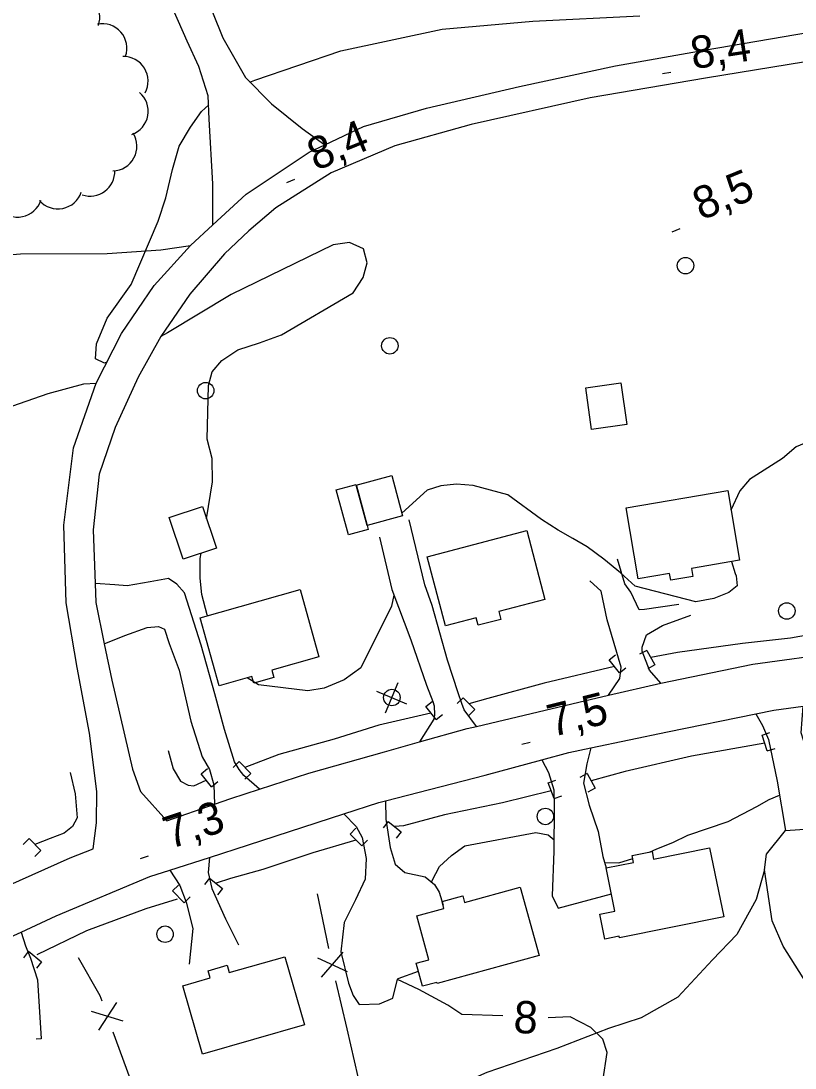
# Model space of a CAD drawing. Extents: x 362852 to 366875, y 5563573 to 5566479.
# Drawn here: x 364831.6 to 364925.6, y 5564861.3 to 5564988.5 of the extents above; entities that cross this region are included whole.
import ezdxf

# ---------------------------------------------------------------- set-up
doc = ezdxf.new("R2010")
doc.units = 0
for name, color, linetype in [('Niveau 19', 7, 'Continuous'), ('Niveau 2', 7, 'Continuous'), ('Niveau 21', 7, 'Continuous'), ('Niveau 22', 7, 'Continuous'), ('Niveau 26', 7, 'Continuous'), ('Niveau 3', 7, 'Continuous'), ('Niveau 31', 7, 'Continuous'), ('Niveau 36', 7, 'Continuous'), ('Niveau 37', 7, 'Continuous'), ('Niveau 4', 7, 'Continuous'), ('Niveau 44', 7, 'Continuous')]:
    doc.layers.add(name, color=color, linetype=linetype)

msp = doc.modelspace()

# ---------------------------------------------------------------- linework, layer by layer
at = {"layer": 'Niveau 19'}
for points in [[(364854.86, 5564963.71), (364854.88, 5564968.69), (364854.45, 5564976.57), (364854.32, 5564979.41), (364853.19, 5564982.96), (364851.76, 5564986.02), (364850.08, 5564989.79)], [(364854.82, 5564989.58), (364856.09, 5564986.44), (364858.84, 5564981.61), (364862, 5564978.41), (364865.72, 5564975.42), (364868.47, 5564973.43)], [(364886.94, 5564902.77), (364885.41, 5564904.8), (364885.15, 5564905.56), (364884.68, 5564906.86), (364883.39, 5564910.83), (364881.52, 5564917.48), (364880.64, 5564919.98), (364878.73, 5564927.86)], [(364875.13, 5564925.75), (364876.64, 5564919.39), (364878.93, 5564913.29), (364880.86, 5564907.78), (364881.62, 5564905.79), (364881.79, 5564905.29), (364881.81, 5564904.18), (364881.73, 5564903.65), (364880.01, 5564900.89)], [(364911.5, 5564917.6), (364907.35, 5564916.98), (364906.71, 5564916.95), (364905.67, 5564919.08), (364904.97, 5564920.11), (364904.08, 5564923.11)], [(364860.54, 5564895.13), (364858.63, 5564896.81), (364858.09, 5564897.52), (364857.51, 5564898.47), (364856.3, 5564902.41), (364855.11, 5564906.74), (364853.45, 5564912.65), (364851.44, 5564919.02), (364850.52, 5564920.07), (364849.49, 5564920.76), (364847.27, 5564920.33), (364844.46, 5564919.84), (364842.98, 5564919.97), (364840.56, 5564920.14)], [(364902.98, 5564906.55), (364904.34, 5564908.61), (364904.49, 5564909.96), (364902.8, 5564915.71), (364902.07, 5564919.21), (364900.69, 5564920.47)], [(364909.33, 5564908.04), (364907.94, 5564909.61), (364907.08, 5564911.91), (364907.07, 5564912.4), (364907.57, 5564913.88), (364909.54, 5564915.04), (364912.97, 5564916.29)], [(364841.68, 5564912.79), (364844.18, 5564913.81), (364846.89, 5564914.77), (364848.29, 5564914.93), (364848.99, 5564914.59), (364849.56, 5564912.85), (364850.79, 5564909.62), (364852.2, 5564903.4), (364853.57, 5564899.06), (364854.46, 5564897.55), (364855, 5564895.66), (364855.09, 5564893.33)], [(364920.89, 5564904.29), (364921.67, 5564902.88), (364922.4, 5564901.18), (364923.49, 5564896.13), (364924.48, 5564890.14), (364927.98, 5564890.37), (364927.08, 5564896.3), (364927.24, 5564899.31), (364926.39, 5564901.97), (364926.62, 5564905.23)], [(364900.83, 5564900.17), (364900.35, 5564898.21), (364899.95, 5564895.87), (364900.62, 5564893.19), (364901.72, 5564890.02), (364902.29, 5564886.97), (364902.68, 5564885.57)], [(364894.85, 5564898.71), (364895.66, 5564897.18), (364896.33, 5564895.05), (364896.38, 5564892.99), (364896.34, 5564887.61), (364896.13, 5564882.19), (364896.84, 5564880.67), (364903.33, 5564882.43)], [(364875.86, 5564893.72), (364875.89, 5564891.48), (364876.44, 5564888.06), (364877.03, 5564886.04), (364878.21, 5564885), (364880.69, 5564884.49), (364881.81, 5564883.58), (364882.38, 5564882.64), (364882.87, 5564881.04)], [(364870.81, 5564892.14), (364872.29, 5564890.6), (364873.01, 5564889.29), (364873.52, 5564886.73), (364873.39, 5564884.21), (364872.2, 5564881.7), (364870.82, 5564878.94), (364870.43, 5564875.37), (364871.37, 5564871.59), (364871.93, 5564870.08), (364872.67, 5564868.98), (364875.15, 5564869.08), (364876.74, 5564869.74), (364877.34, 5564872.04), (364877.42, 5564872.14), (364879.86, 5564873.04)], [(364854.49, 5564886.86), (364854.32, 5564885.02), (364854.75, 5564883.08), (364856.41, 5564879.38), (364857.98, 5564876.21)], [(364849.64, 5564885.3), (364850.85, 5564883.44), (364851.63, 5564881.4), (364852.43, 5564878.23), (364851.98, 5564873.89)], [(364831.57, 5564877.78), (364832.09, 5564876.11), (364832.7, 5564874.6), (364833.56, 5564871.98), (364834, 5564864.79), (364833.41, 5564864.78)]]:
    msp.add_lwpolyline(points, dxfattribs=at)
at = {"layer": 'Niveau 2'}
for points in [[(364859.38, 5564981.06), (364859.99, 5564981.31), (364870.43, 5564984.88), (364882.75, 5564987.49), (364893.77, 5564988.45), (364906.77, 5564989.1)], [(364842, 5564947.04), (364841.69, 5564946.91), (364840.6, 5564947.45), (364840.72, 5564949.25), (364842.03, 5564952.39), (364844.94, 5564956.46), (364848.22, 5564964.15), (364849.15, 5564967.01), (364849.96, 5564970.46), (364850.78, 5564973.28), (364852.18, 5564975.6), (364853.5, 5564977.51), (364854.37, 5564978.3)], [(364860.53, 5564949.36), (364863.22, 5564950.35), (364871.92, 5564955.44), (364873.13, 5564957.31), (364873.62, 5564959.12), (364873.17, 5564960.8), (364871.48, 5564961.59), (364869.51, 5564961.27), (364857.1, 5564955.27), (364849.36, 5564950.58), (364848.56, 5564950.14)], [(364854.12, 5564928.01), (364854.84, 5564932.48), (364854.79, 5564935.31), (364854.19, 5564937.67), (364854.35, 5564944.2), (364854.78, 5564945.86), (364855.95, 5564947.22), (364857.9, 5564948.52), (364860.53, 5564949.36)], [(364931.23, 5564933.18), (364930.52, 5564935.46), (364928.65, 5564937.3), (364927.26, 5564937.34), (364925.78, 5564936.73), (364924.14, 5564935.31), (364920.1, 5564932.77), (364918.92, 5564931.41), (364917.86, 5564929.06)], [(364917.94, 5564922.8), (364918.36, 5564921.36), (364918.49, 5564921.05), (364918.61, 5564919.85), (364917.58, 5564919.05), (364915.77, 5564918.31), (364913.59, 5564917.9), (364906.22, 5564919.82), (364904.43, 5564921.44), (364902.39, 5564923.08), (364900.39, 5564924.61), (364898.62, 5564925.62), (364896.84, 5564926.62), (364894.82, 5564927.9), (364890.72, 5564930.92), (364886.53, 5564932.05), (364884.49, 5564932.19), (364882.57, 5564932.02), (364880.94, 5564931.47), (364877.86, 5564928.68)], [(364854.23, 5564916.24), (364854.2, 5564916.31), (364853.55, 5564918.78), (364853.34, 5564920.8), (364853.35, 5564923.17), (364853.45, 5564923.81)], [(364876.89, 5564918.71), (364876.59, 5564917.37), (364872.86, 5564909.87), (364870.86, 5564908.42), (364868.42, 5564907.41), (364866.44, 5564907.09), (364860.43, 5564907.83), (364859.06, 5564908.67)], [(364907.94, 5564887.5), (364908.86, 5564887.88), (364910.77, 5564888.66), (364912.63, 5564889.56), (364917.53, 5564891.21), (364921, 5564893.02), (364922.5, 5564893.89), (364923.77, 5564894.42)], [(364881.5, 5564883.83), (364881.55, 5564884.03), (364882.44, 5564885.76), (364883.88, 5564887.1), (364885.5, 5564888.27), (364894.15, 5564889.86), (364895.62, 5564889.6), (364896.35, 5564889)], [(364902.5, 5564886.22), (364904.22, 5564886.2), (364905.91, 5564886.72)], [(364890.14, 5564867.61), (364885.16, 5564867.76), (364883.44, 5564868.91), (364879.93, 5564870.81), (364877.94, 5564871.73), (364877.34, 5564872.02)], [(364902.27, 5564859.68), (364902.82, 5564863.14), (364902.27, 5564864.78), (364900.83, 5564866.17), (364898.3, 5564867.48), (364895.65, 5564867.37)]]:
    msp.add_lwpolyline(points, dxfattribs=at)
at = {"layer": 'Niveau 21'}
for points in [[(364840.31, 5564887.88), (364840.72, 5564891.07), (364840.79, 5564894.85), (364839.88, 5564901.95), (364838.37, 5564909.91), (364837.05, 5564917.77), (364836.78, 5564927.24), (364837.94, 5564936.62), (364840.71, 5564944.48), (364843.77, 5564950.53), (364847.74, 5564956.34), (364852.15, 5564961.22), (364854.86, 5564963.71), (364858.91, 5564967.44), (364866.58, 5564972.54), (364868.47, 5564973.43), (364873.2, 5564975.66), (364880.86, 5564977.9), (364892.17, 5564980.53), (364903.82, 5564983.04), (364914.6, 5564984.95), (364927.39, 5564987.13), (364940.08, 5564988.46), (364954.57, 5564989.62)], [(364930.88, 5564984.16), (364914.75, 5564981.54), (364900.76, 5564979.17), (364886.28, 5564975.93), (364876.98, 5564973.32), (364869.24, 5564970.05), (364862.54, 5564965.78), (364859.25, 5564962.99), (364856.28, 5564960.2), (364852.07, 5564955.28), (364848.57, 5564950.16), (364845.8, 5564945.22), (364842.99, 5564939.09), (364841.04, 5564933.42), (364840.33, 5564926.65), (364840.56, 5564920.14), (364840.65, 5564917.83), (364841.68, 5564912.79), (364842.59, 5564908.37), (364845.11, 5564897.58), (364846.07, 5564894.86), (364849.29, 5564891.31)], [(364849.29, 5564891.31), (364855.09, 5564893.33), (364857.06, 5564894.02), (364860.54, 5564895.13), (364866.54, 5564897.07), (364875.73, 5564899.7), (364880.01, 5564900.89), (364885.8, 5564902.5), (364886.94, 5564902.77), (364899.35, 5564905.7), (364902.98, 5564906.55), (364909.33, 5564908.04), (364920.52, 5564910.32), (364931.16, 5564911.81), (364939.02, 5564912.98), (364945.51, 5564913.95), (364954.89, 5564914.62), (364958.04, 5564914.85), (364962.78, 5564915.16), (364967.33, 5564915.46), (364973.94, 5564915.83), (364977.36, 5564916.03), (364989.51, 5564916.41), (364998.46, 5564916.49)], [(364827.38, 5564875.85), (364831.57, 5564877.78), (364835.85, 5564879.76), (364847.22, 5564884.53), (364849.64, 5564885.3), (364854.49, 5564886.86), (364859.2, 5564888.38), (364870.81, 5564892.14), (364875.05, 5564893.52), (364875.86, 5564893.72), (364887.99, 5564896.83), (364894.85, 5564898.71), (364898.14, 5564899.6), (364900.83, 5564900.17), (364910.14, 5564902.11), (364920.89, 5564904.29), (364923.08, 5564904.73), (364926.62, 5564905.23)], [(364829.85, 5564883.35), (364837.53, 5564886.79), (364840.31, 5564887.88)]]:
    msp.add_lwpolyline(points, dxfattribs=at)
at = {"layer": 'Niveau 22'}
for points in [[(364793.73, 5564950.34), (364799.32, 5564952.65), (364803.9, 5564954.39), (364808.18, 5564955.75), (364820.42, 5564959.27), (364831.51, 5564960.2), (364842.03, 5564960.22), (364848.54, 5564960.7), (364852.15, 5564961.22)], [(364782.44, 5564942.02), (364785.31, 5564940.9), (364787.9, 5564939.43), (364789.49, 5564938.7), (364792.51, 5564937.2), (364797.93, 5564935.27), (364801.74, 5564934.48), (364810.07, 5564935.5), (364820.5, 5564938.4), (364829.62, 5564941.41), (364834.87, 5564943.23), (364839.2, 5564944.41), (364840.71, 5564944.48)], [(365020.02, 5564865.79), (365014.94, 5564866.34), (365007.86, 5564865.87), (364995.41, 5564864.38), (364983.3, 5564862.86), (364972.1, 5564861.76), (364961.45, 5564860.83), (364955.92, 5564859.76), (364952.98, 5564858.92), (364950.44, 5564858.17), (364948.74, 5564858.09), (364943.36, 5564858.58), (364938.36, 5564859.06), (364934.59, 5564859.41), (364933.55, 5564859.97), (364932.52, 5564860.97), (364931.14, 5564863.62), (364929.76, 5564866.52), (364928.08, 5564869.91), (364924.21, 5564876.05), (364922.85, 5564879.14), (364921.92, 5564885.35), (364922.19, 5564887.26), (364924.48, 5564890.14)], [(364921.92, 5564885.35), (364920.9, 5564881.75), (364918.56, 5564877.49), (364915.62, 5564874.41), (364911.41, 5564869.87), (364906.94, 5564867.34), (364902.99, 5564866.08), (364896.7, 5564863.64), (364888.2, 5564860.73), (364885.33, 5564859.48), (364879.23, 5564856.81), (364873.61, 5564854.18), (364866.25, 5564851.93), (364860.8, 5564850.77), (364848.56, 5564849.72), (364841.14, 5564848.19), (364831.86, 5564845.06), (364821.27, 5564841.41), (364820.46, 5564841.14), (364809.21, 5564837.9), (364799.25, 5564836.01), (364795.21, 5564835.22)]]:
    msp.add_lwpolyline(points, dxfattribs=at)
at = {"layer": 'Niveau 26'}
for p, q in [((364907.63, 5564912.01), (364906.75, 5564911.53)), ((364907.63, 5564912.01), (364908.6, 5564910.25)), ((364903.04, 5564910.85), (364903.83, 5564911.47)), ((364904.31, 5564909.27), (364903.04, 5564910.85)), ((364904.31, 5564909.27), (364905.09, 5564909.9)), ((364908.6, 5564910.25), (364907.74, 5564909.77)), ((364880.76, 5564905.17), (364881.53, 5564905.79)), ((364885.3, 5564906.24), (364884.59, 5564905.54)), ((364885.3, 5564906.24), (364886.72, 5564904.81)), ((364882.03, 5564903.59), (364880.76, 5564905.17)), ((364882.03, 5564903.59), (364882.81, 5564904.21)), ((364886.72, 5564904.81), (364886.01, 5564904.11)), ((364921.63, 5564901.72), (364922.59, 5564902.02)), ((364922.26, 5564899.79), (364921.63, 5564901.72)), ((364922.26, 5564899.79), (364923.22, 5564900.1)), ((364858.06, 5564898.5), (364857.35, 5564897.78)), ((364858.06, 5564898.5), (364859.49, 5564897.05)), ((364853.46, 5564897), (364854.22, 5564897.64)), ((364854.72, 5564895.44), (364853.46, 5564897)), ((364859.49, 5564897.05), (364858.78, 5564896.35)), ((364900.36, 5564897.03), (364899.5, 5564896.55)), ((364900.36, 5564897.03), (364901.35, 5564895.27)), ((364854.72, 5564895.44), (364855.5, 5564896.06)), ((364895.62, 5564895.9), (364896.57, 5564896.24)), ((364896.35, 5564894.02), (364895.62, 5564895.9)), ((364901.35, 5564895.27), (364900.47, 5564894.78)), ((364896.35, 5564894.02), (364897.29, 5564894.35)), ((364871.55, 5564889.69), (364872.26, 5564890.39)), ((364876.2, 5564891.21), (364875.57, 5564890.43)), ((364876.2, 5564891.21), (364877.78, 5564889.97)), ((364832.55, 5564889.13), (364831.82, 5564888.42)), ((364832.55, 5564889.13), (364833.96, 5564887.69)), ((364872.98, 5564888.24), (364871.55, 5564889.69)), ((364872.98, 5564888.24), (364873.69, 5564888.96)), ((364877.78, 5564889.97), (364877.16, 5564889.18)), ((364833.96, 5564887.69), (364833.25, 5564886.98)), ((364854.48, 5564884.34), (364853.87, 5564883.55)), ((364854.48, 5564884.34), (364856.06, 5564883.08)), ((364849.99, 5564882.79), (364850.7, 5564883.49)), ((364851.4, 5564881.35), (364849.99, 5564882.79)), ((364856.06, 5564883.08), (364855.46, 5564882.3)), ((364851.4, 5564881.35), (364852.11, 5564882.05)), ((364832.46, 5564875.44), (364831.85, 5564874.65)), ((364832.46, 5564875.44), (364834.04, 5564874.18)), ((364834.04, 5564874.18), (364833.44, 5564873.4))]:
    msp.add_line(p, q, dxfattribs=at)
at = {"layer": 'Niveau 3'}
for p, q in [((364909.52, 5564982.12), (364910.55, 5564982.28)), ((364863.87, 5564968.88), (364864.83, 5564969.27)), ((364910.72, 5564962.87), (364911.68, 5564963.26)), ((364892.42, 5564900.61), (364893.43, 5564900.86)), ((364846.08, 5564886.71), (364847.06, 5564887.04))]:
    msp.add_line(p, q, dxfattribs=at)
at = {"layer": 'Niveau 31'}
for points in [[(364904.48, 5564944.51), (364905.18, 5564939.46), (364900.91, 5564938.86), (364900.2, 5564943.91), (364904.48, 5564944.51)], [(364872.29, 5564932.16), (364873.64, 5564927.19), (364873.77, 5564926.68), (364871.36, 5564926.03), (364869.88, 5564931.51), (364872.29, 5564932.16)], [(364905.12, 5564929.32), (364917.46, 5564931.42), (364918.89, 5564922.96), (364913.06, 5564921.97), (364913.23, 5564921), (364910.53, 5564920.54), (364910.39, 5564921.35), (364906.58, 5564920.71), (364905.12, 5564929.32)], [(364853.62, 5564929.5), (364855.33, 5564924.44), (364851.29, 5564923.08), (364849.58, 5564928.14), (364853.62, 5564929.5)], [(364880.94, 5564923.37), (364893.03, 5564926.56), (364895.24, 5564918.21), (364889.62, 5564916.72), (364889.87, 5564915.78), (364887.13, 5564915.06), (364886.89, 5564915.96), (364883.16, 5564914.98), (364880.94, 5564923.37)], [(364853.32, 5564915.98), (364865.48, 5564919.39), (364867.77, 5564911.21), (364862.06, 5564909.6), (364862.31, 5564908.72), (364859.86, 5564908.03), (364859.63, 5564908.83), (364855.64, 5564907.71), (364853.32, 5564915.98)], [(364915.26, 5564888.02), (364916.97, 5564879.65), (364904.31, 5564877.06), (364904.26, 5564877.29), (364902.52, 5564876.93), (364901.91, 5564879.95), (364903.76, 5564880.32), (364902.68, 5564885.57), (364906.01, 5564886.25), (364905.84, 5564887.07), (364908.26, 5564887.56), (364908.45, 5564886.63), (364915.26, 5564888.02)], [(364880.36, 5564871.2), (364879.59, 5564874), (364881.14, 5564874.42), (364879.68, 5564879.75), (364882.97, 5564880.65), (364882.74, 5564881.5), (364885.26, 5564882.19), (364885.48, 5564881.38), (364892.25, 5564883.24), (364894.53, 5564874.92), (364882.14, 5564871.52), (364882.1, 5564871.67), (364880.36, 5564871.2)], [(364854.31, 5564873.09), (364856.62, 5564873.76), (364856.88, 5564872.85), (364863.62, 5564874.79), (364866.02, 5564866.5), (364853.64, 5564862.93), (364851.24, 5564871.24), (364854.57, 5564872.21), (364854.31, 5564873.09)]]:
    msp.add_lwpolyline(points, dxfattribs=at)
msp.add_lwpolyline([(364876.62, 5564933.27), (364877.95, 5564928.36), (364873.64, 5564927.19), (364872.31, 5564932.1), (364876.62, 5564933.27)], close=True, dxfattribs=at)
at = {"layer": 'Niveau 36'}
for p, q in [((364875.86, 5564904.42), (364877.41, 5564908.09)), ((364878.47, 5564905.48), (364874.8, 5564907.03))]:
    msp.add_line(p, q, dxfattribs=at)
for centre in [(364912.33, 5564958.76), (364876.39, 5564949.02), (364854, 5564943.57), (364924.64, 5564916.8), (364876.64, 5564906.28), (364895.3, 5564891.83), (364849.07, 5564877.52)]:
    msp.add_circle(centre, 1, dxfattribs=at)
at = {"layer": 'Niveau 37'}
for p, q in [((364867.75, 5564881.65), (364867.59, 5564882.42)), ((364868.98, 5564875.78), (364867.75, 5564881.65)), ((364868.08, 5564872.32), (364870.72, 5564875.32)), ((364867.59, 5564874.66), (364871.21, 5564872.97)), ((364871.19, 5564866.03), (364869.84, 5564871.87)), ((364843.15, 5564869.23), (364840.96, 5564865.88)), ((364843.97, 5564866.97), (364840.14, 5564868.14)), ((364872.54, 5564860.18), (364871.19, 5564866.03)), ((364842.74, 5564865.67), (364844.79, 5564860.03))]:
    msp.add_line(p, q, dxfattribs=at)
msp.add_lwpolyline([(364838.49, 5564874.68), (364841.14, 5564870.09), (364841.38, 5564869.43)], dxfattribs=at)
at = {"layer": 'Niveau 4'}
for points in [[(364931, 5564914.54), (364925.08, 5564913.48), (364919.26, 5564912.85), (364911.34, 5564911.75), (364908.11, 5564911.15)], [(364903.69, 5564910.05), (364895.15, 5564908.02), (364888.3, 5564906.17), (364886, 5564905.53)], [(364881.39, 5564904.37), (364875.05, 5564902.93), (364869.63, 5564901.23), (364862.88, 5564899.37), (364858.78, 5564897.78)], [(364921.96, 5564900.75), (364913.06, 5564899.16), (364904.98, 5564897.29), (364900.86, 5564896.17)], [(364849.43, 5564899.85), (364850.07, 5564897.61), (364850.96, 5564896.11), (364851.88, 5564895.63), (364852.55, 5564895.53), (364854.08, 5564896.22)], [(364837.53, 5564897.15), (364838.14, 5564894.58), (364838.4, 5564891.65), (364837.8, 5564890.59), (364836.82, 5564889.81), (364835.1, 5564889.13), (364833.25, 5564888.42)], [(364895.99, 5564894.95), (364890.07, 5564893.47), (364883.03, 5564892.02), (364878.06, 5564890.68), (364876.99, 5564890.6)], [(364872.26, 5564888.96), (364867.05, 5564887.4), (364860.96, 5564885.39), (364857.04, 5564884.28), (364855.27, 5564883.71)], [(364850.56, 5564881.79), (364846.74, 5564880.62), (364839.5, 5564877.92), (364833.49, 5564875)]]:
    msp.add_lwpolyline(points, dxfattribs=at)
at = {"layer": 'Niveau 44'}
for centre, start, end in [((364838.13, 5564988.91), 341.3797, 101.3576), ((364841.43, 5564985.16), 341.3797, 101.3576), ((364844, 5564981.19), 331.2789, 91.2569), ((364844.02, 5564977.52), 289.8228, 49.8007), ((364842.65, 5564973.27), 271.7285, 31.7065), ((364839.96, 5564970.2), 251.1461, 2.3748), ((364831.14, 5564967.66), 221.4812, 341.4591), ((364836.04, 5564968.65), 221.4812, 341.4591)]:
    msp.add_arc(centre, 3, start, end, dxfattribs=at)

# ---------------------------------------------------------------- texts
at = {"layer": 'Niveau 2'}
msp.add_text('8', height=3.93, rotation=357.2362, dxfattribs=at).set_placement((364891.37, 5564865.54))
at = {"layer": 'Niveau 3'}
for s, rotation, p in [('8,4  ', 8.631, (364913.25, 5564982.62)), ('8,4  ', 22.09, (364867.38, 5564970.24)), ('8,5  ', 22.09, (364914.23, 5564964.23)), ('7,5  ', 13.9445, (364896.09, 5564901.46)), ('7,3  ', 18.3811, (364849.67, 5564887.84))]:
    msp.add_text(s, height=3.93, rotation=rotation, dxfattribs=at).set_placement(p)

doc.saveas('drawing.dxf')
